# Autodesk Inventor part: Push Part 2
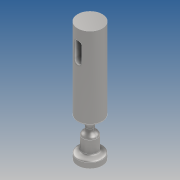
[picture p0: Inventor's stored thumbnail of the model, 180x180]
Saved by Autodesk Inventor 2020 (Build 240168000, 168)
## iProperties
Created: 2019-10
Part Number: Push Part 2
Material: Generic
Document SubType Name: Modeling
Designer: yello
Density: 1 g/cm^3
Appearance: Default
Author: yello
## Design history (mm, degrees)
sketch "Sketch2" dims "d4" = 3
  geometry: L1 (0, 0)-(2, 0); L2 (0, 0)-(0, -26); L3 (0, -26)-(2.5, -26); L4 (2.5, -26)-(2.5, -24); L5 (2.5, -24)-(3.5, -24); L6 (0, -26)-(0, -28); L7 (0, -28)-(2, -28); L8 (2, -24)-(2, 0); L9 (0, -28)-(0, -32.5); L10 (2, -28)-(2, -30); L11 (0, -32.5)-(2, -32.5); L12 (2, -32.5)-(2, -30); L13 (2, -28)-(2, -27.177); L14 (2, -27.177)-(1, -27.177); L15 (1, -27.177)-(1, -26); L16 (2, -24)-(2, -24.823); L17 (2, -24.823)-(1, -24.823); L18 (1, -24.823)-(1, -26); L19 (2, -31.5)-(2, -34); L20 (3.5, -32.5)-(3.5, -34); L21 (3.5, -34)-(2, -34); L22 (2, -34)-(0, -34); L23 (0, -34)-(0, -32.5); L24 (2, -31.5)-(2, -32.5); L25 (2, -31.5)-(2, -32); L26 (2, -32)-(3.5, -32); L27 (3.5, -32)-(3.5, -32.5); L28 (2, -24)-(2, -23); L29 (2, 0)-(3.5, 0); L30 (3.5, 0)-(3.5, -23.002); L31 (2, -24)-(2, -23.5); L32 (2, -23.5)-(3.5, -23.501); L33 (3.5, -23.501)-(3.5, -23.002)
  constraints: 42 end point, 9 perpendicular, 6 point on line, 6 vertical, 5 horizontal, 3 symmetric about line, 2 midpoint, 1 coincident, 1 horizontal alignment, 14 other
  dimensions: "d0" = 2 distance of L1.start L1.end; "d2" = 26 distance of L1.start L2.end; "d7" = 2 distance of L4.start L4.end; "d8" = 1.5 distance of L5.end L8.start; "d9" = 4.5 distance of L6.end L9.end; "d10" = 2 distance of L7.end L10.end; "d11" = 2.5 distance of L2.end L3.end; "d13" = 2.5 distance of L19.start L19.end; "d15" = 1 distance of L8.start L28.end; "d16" = 1.5 distance of L1.end L29.end; "d25" = 4 distance from line of L10.end L3
revolve "Revolution1" sketch "Sketch2" stored, may be unused: angle "d17" = 90 deg
workplane "Work Plane1"
sketch "Sketch3"
  geometry: L1 (0, 0)-(0, -4); L2 (0, -4)-(0, -8); L3 (-1, -4)-(-1, -8); L4 (1, -8)-(1, -4); C1 r 1 at (0, -4); A1 r 1 centre (0, -4) between (1, -4) and (-1, -4); A2 r 1 centre (0, -8) between (-1, -8) and (1, -8); 3 further points
  constraints: 10 end point, 4 point on circle, 4 tangent, 3 centre point, 2 vertical, 1 coincident, 1 concentric, 1 midpoint, 1 parallel
  dimensions: "d19" = 4 distance of L1.start L1.end; "d20" = 2 diameter of C1; "d26" = 4 distance of L2.start L2.end
extrude "Extrusion2" cut sketch "Sketch3" distance "d27" = 10; taper "d28" = 0 deg
body "Solid1"
other parameters: "d18" = 3.5
